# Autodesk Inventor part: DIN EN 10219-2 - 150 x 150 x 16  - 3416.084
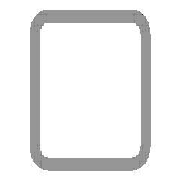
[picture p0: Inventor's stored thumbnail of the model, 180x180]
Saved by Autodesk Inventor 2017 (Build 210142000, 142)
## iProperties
IsCustomPart: 1
_CCFamilyMember: 76
_CCFamilyDisplayName: DIN EN 10219-2 (Square Hollow Section - Cold Formed) - Cold formed welded structural hollow sections of non-alloy and fine grain structural steel
_FrameMemberDoc: Frame Member File
_Version: 15.0.0
_GetPNFromCC: 1
Created: 2017-11
Part Number: DIN EN 10219-2 - 150 x 150 x 16  - 3416.084
Material: Steel, Mild
Description: Cold formed welded structural hollow sections of non-alloy and fine grain structural steel
Document SubType Name: Modeling
Standard: DIN
Designer: iusti
Standard Revision: 2006-07
Standards Organization: DIN
Language: en-US
Size Designation: 150 x 150 x 16
Categories: <MemberInstance><Categories><Category DisplayName="Structural Shapes" InternalName="089c4875-fa83-4c05-b084-43b9cc11f5ed" Mnemonic="GRDR"><CategoryParameter Dis
Stock Number: 150 x 150 x 16
Density: 7.85 g/cm^3
Appearance: Semi-Polished
Mass: 187360 g
Surface Area: 30123 cm^2
Volume: 23867.5 cm^3
G_L: 3416.084 mm
G_W: 150.000 mm
G_H: 150.000 mm
+4654C135-6D8C-4950-BBE2-01DB03A734B6+CUTDETAIL1: Cut
+D2B28E9A-99E0-4240-A9A6-2079430655EE+CUTDETAIL2: Cut
Author: iusti
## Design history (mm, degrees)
node "Start plane"
node "End plane"
sketch "Sketch"
  geometry: L1 (-75, -27)-(-75, 27); L2 (-27, 75)-(27, 75); L3 (75, 27)-(75, -27); L4 (27, -75)-(-27, -75); L5 (-27, 59)-(27, 59); L6 (59, 27)-(59, -27); L7 (27, -59)-(-27, -59); L8 (-59, -27)-(-59, 27); L9 (0, 118.918)-(0, -118.918) reference; L10 (-118.918, 0)-(118.918, 0) reference; A1 r 48 centre (-27, -27) between (-75, -27) and (-27, -75); A2 r 48 centre (-27, 27) between (-27, 75) and (-75, 27); A3 r 48 centre (27, 27) between (75, 27) and (27, 75); A4 r 48 centre (27, -27) between (27, -75) and (75, -27); A5 r 32 centre (-27, 27) between (-27, 59) and (-59, 27); A6 r 32 centre (27, 27) between (59, 27) and (27, 59); A7 r 32 centre (27, -27) between (27, -59) and (59, -27); A8 r 32 centre (-27, -27) between (-59, -27) and (-27, -59)
  constraints: 16 end point, 16 point on circle, 8 centre point, 8 tangent, 4 parallel, 3 equal radius, 2 perpendicular, 7 other
  dimensions: "d7" = 48 radius of A1 (= G_IR); "d10" = 150 distance between parallel lines of L2 L4 (= G_H); "d11" = 150 distance between parallel lines of L1 L3 (= G_W); "d12" = 16 distance between parallel lines of L3 L6 (= G_T); "d15" = 75 distance between parallel lines of L2 L10 (= 0.5 x d10); "d16" = 75 distance between parallel lines of L9 L3 (= 0.5 x d11)
extrude "Body" new body sketch "Sketch" stored distance "d3" = 3416.08372 (= G_L); taper "d4" = 0 deg
node "Driven Length"
  sketch "Sketch3"
    geometry: L1 (0, 0)-(10, 0) reference
    constraints: 2 end point, 1 horizontal
  workplane "Work Plane3"
  sketch "Sketch4"
    geometry: L1 (-2, 55.969)-(12, 55.969) reference; L2 (-2, 3472.052)-(12, 3472.052) reference
    dimensions: "d18" = 3416.08372 distance between parallel lines of L1 L2 (derived)
workplane "Work Plane4"
split "Split1"
workplane "Work Plane5"
split "Split2"
body "Solid1"
other parameters: "G_W" = 150 [user parameter; used in 1 equation term], "G_H" = 150 [user parameter; used in 1 equation term], "G_T" = 16 [user parameter; used in 1 equation term], "G_IR" = 48 [user parameter; used in 1 equation term], "G_L" = 3416.08372 (= d18) [user parameter; used in 1 equation term], "G_OFFSET_START" = -55.96865 [user parameter; used in 1 equation term], "G_OFFSET_END" = -13.90929 [user parameter; used in 1 equation term], "d13" = 55.96865 (= -G_OFFSET_START), "d14" = 3472.05237 (= G_OFFSET_END + B_L), "B_L" = 3485.96166 [user parameter; used in 1 equation term], "d17" = 90 deg
